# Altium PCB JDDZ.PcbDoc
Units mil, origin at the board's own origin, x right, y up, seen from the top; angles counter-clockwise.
Board outline 2165.35 x 2165.35 mil, 2 copper layers (Top Layer, Bottom Layer); 69 components, 50 nets, 275 pads, 93 vias.
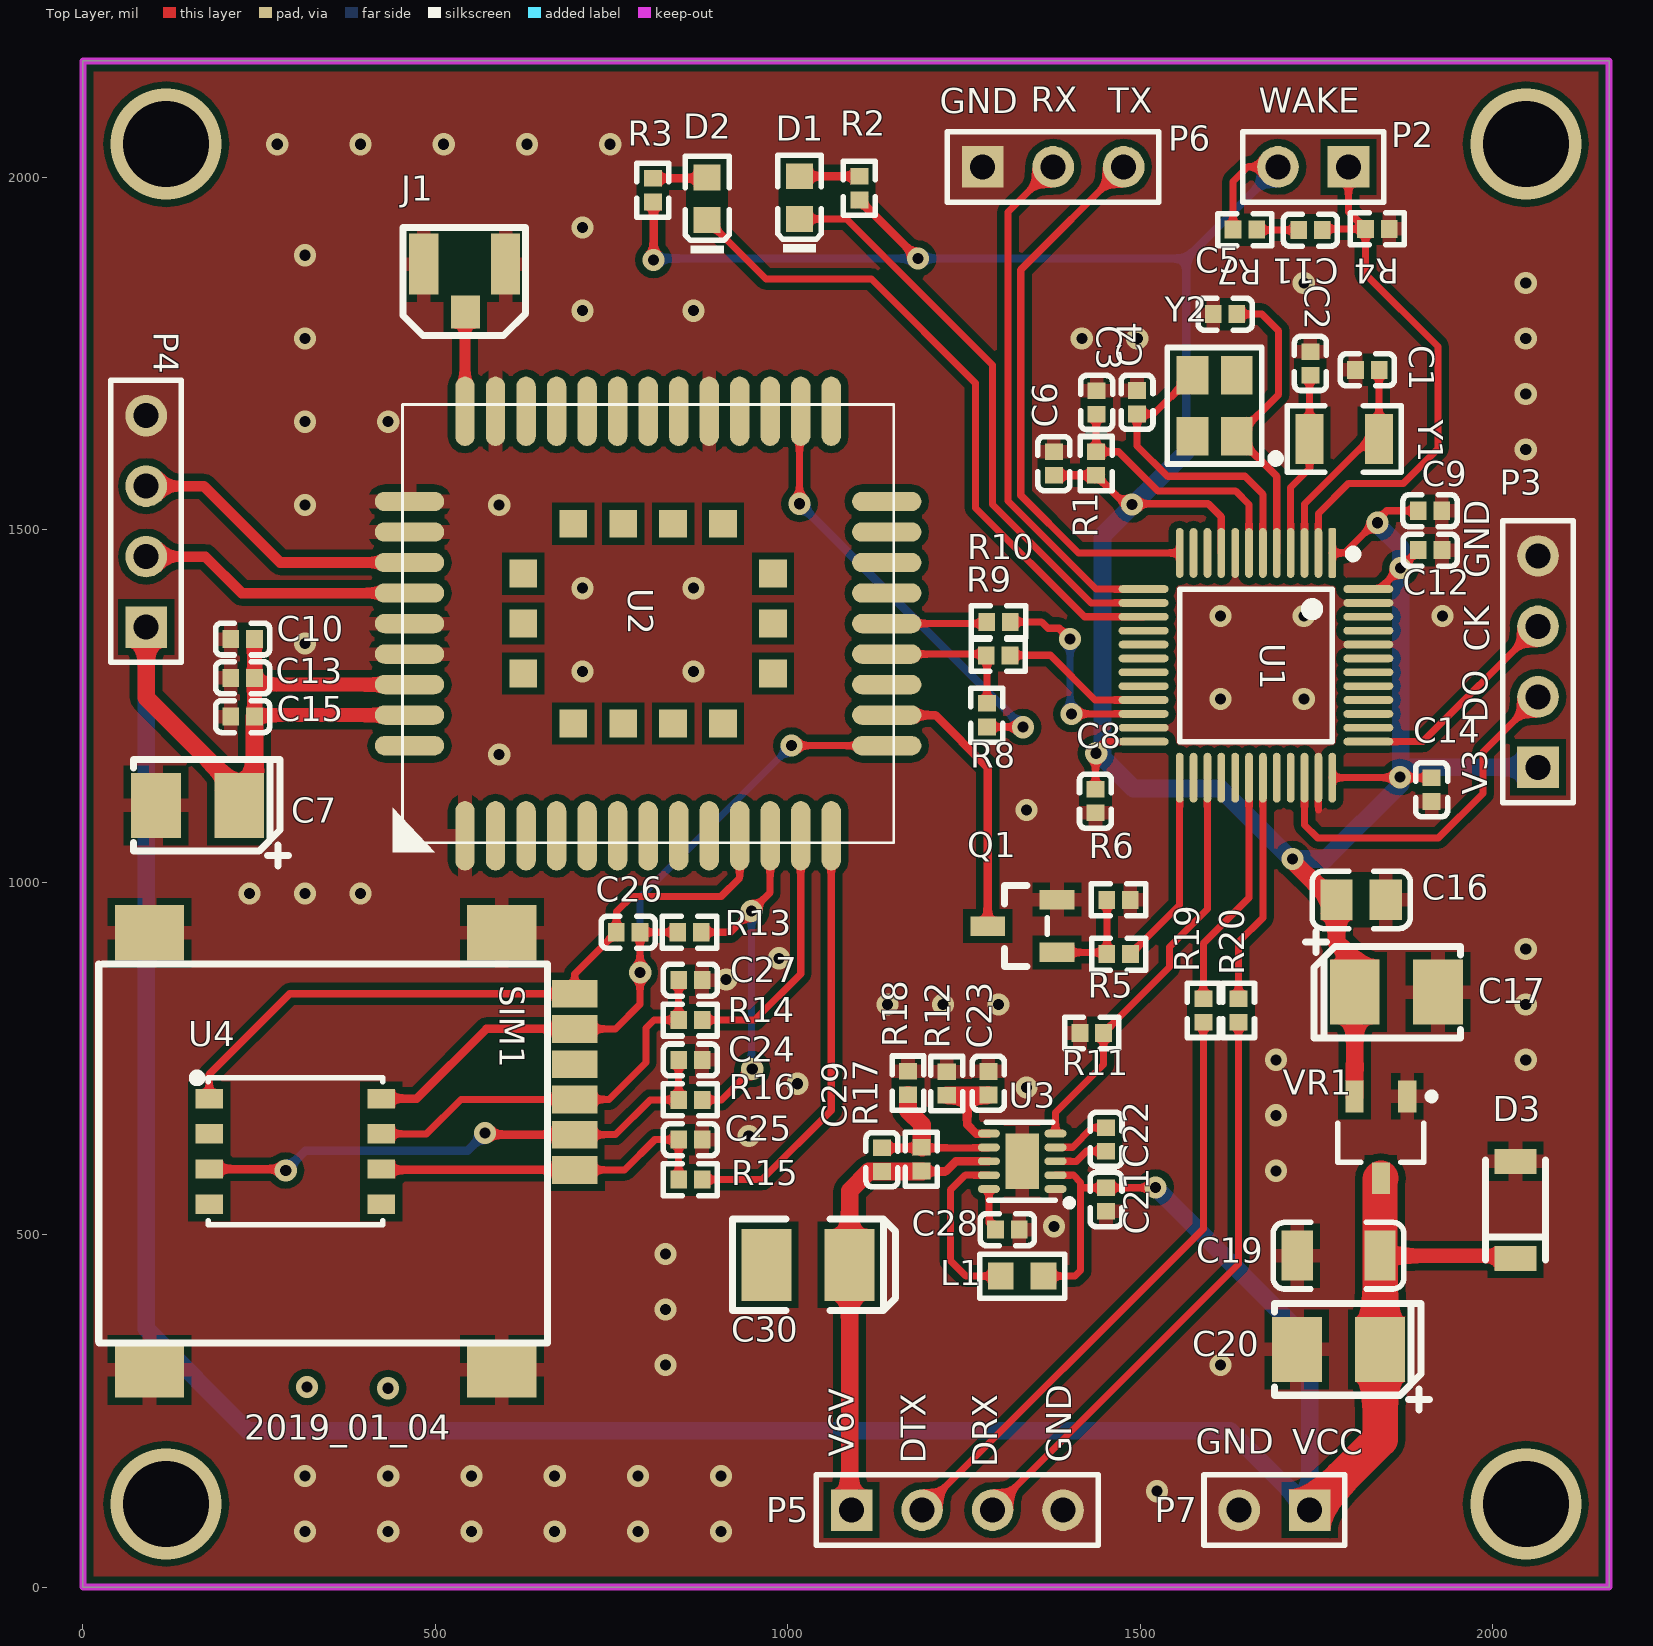
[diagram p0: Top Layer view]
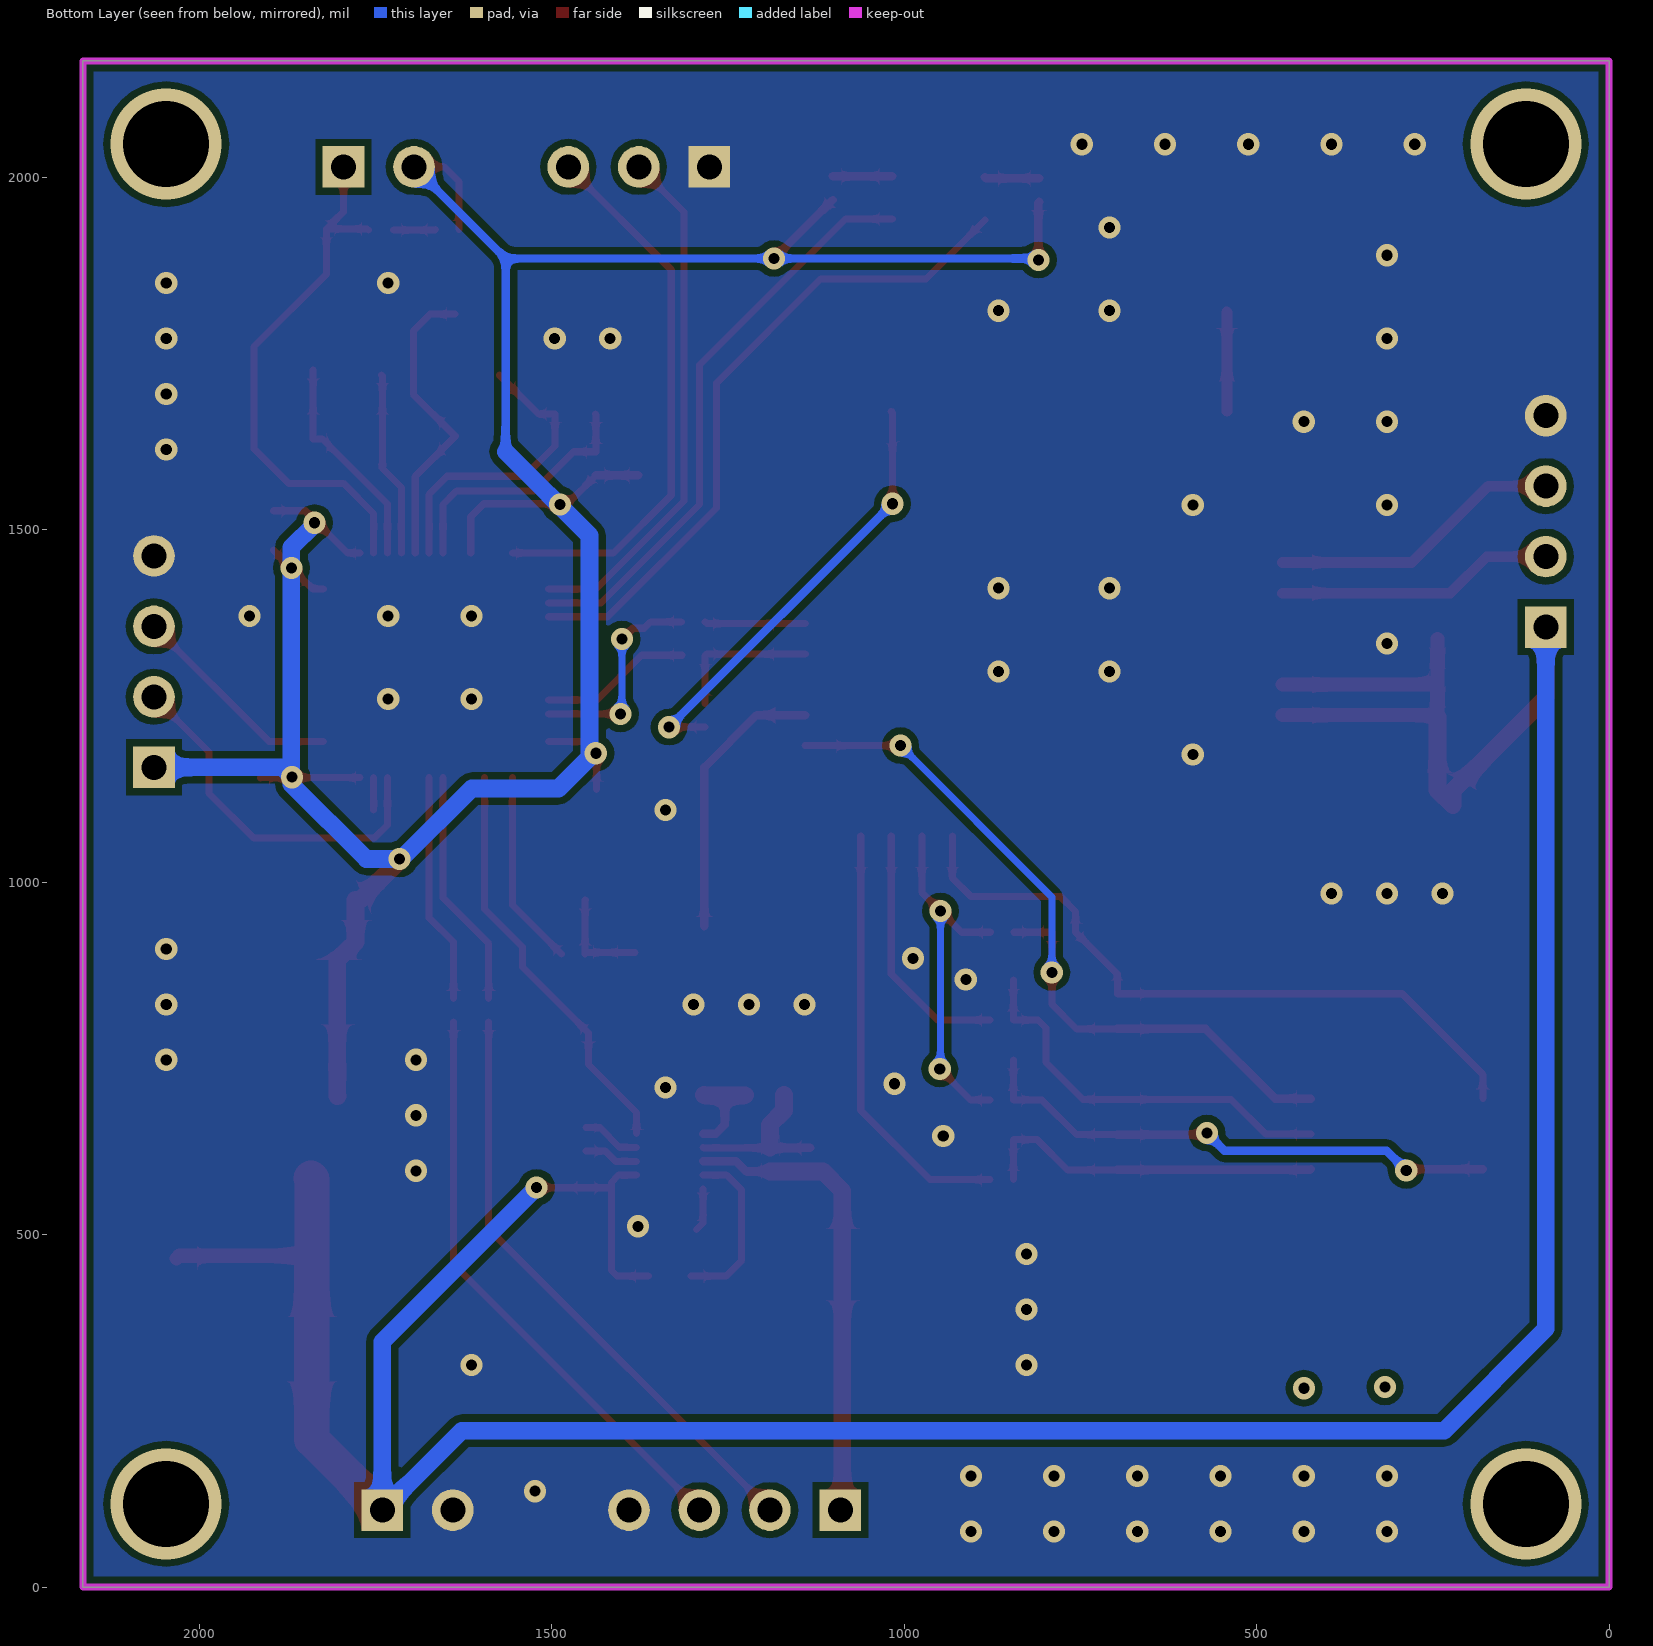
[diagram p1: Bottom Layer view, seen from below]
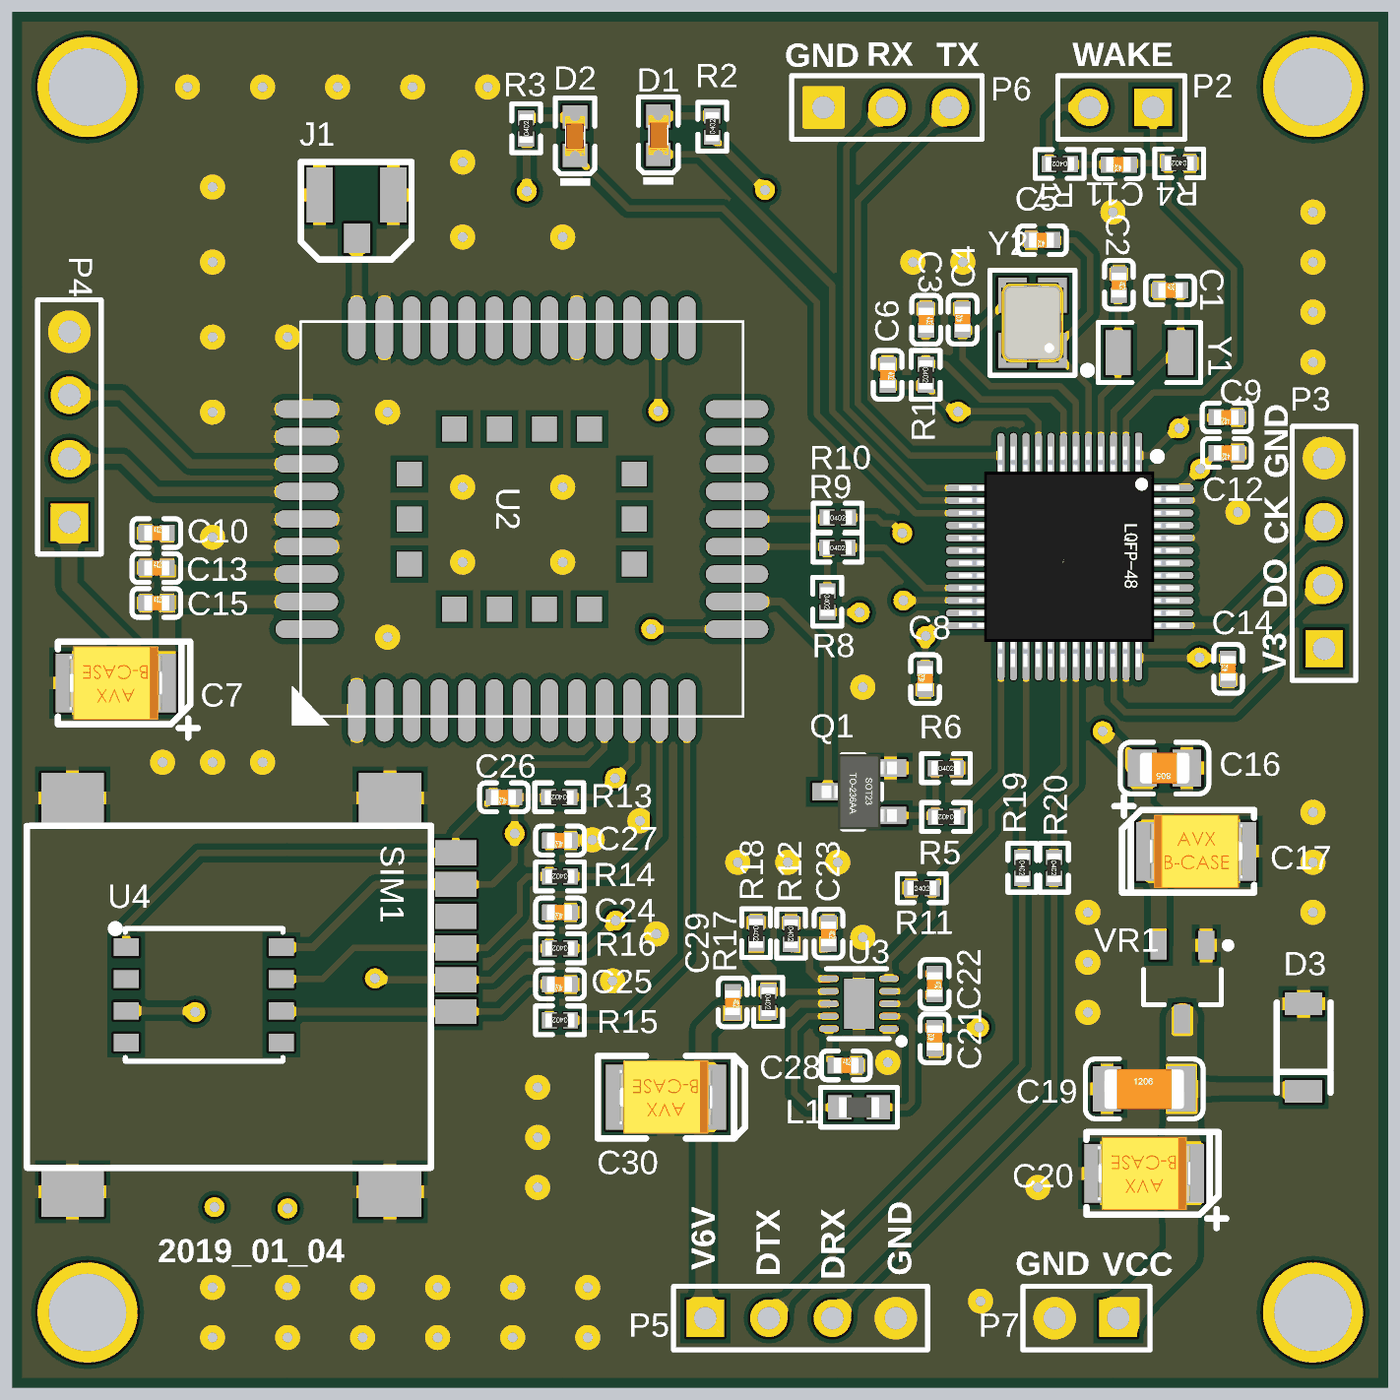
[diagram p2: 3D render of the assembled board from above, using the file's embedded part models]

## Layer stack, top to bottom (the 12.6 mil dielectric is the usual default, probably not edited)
Top Solder: solder mask 0.4, Solder Resist, Dk 3.5
Top Layer: signal copper 1.4
Dielectric 1: dielectric 12.6, FR-4, Dk 4.8
Bottom Layer: signal copper 1.4
Bottom Solder: solder mask 0.4, Solder Resist, Dk 3.5

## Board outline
0,0 0,2165.35 2165.35,2165.35 2165.35,0

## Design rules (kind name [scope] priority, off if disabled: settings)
Clearance Clearance_7 [InNamedPolygon('Top Layer-No Net 1')] p1: gap=10 ignorepadtopadclearanceinfootprint=FALSE except(0: Arc-Hole Track-Hole SMDPad-Hole THPad-Hole Via-Hole Fill-Hole Poly-Hole Region-Hole Text-Hole)
Clearance Clearance_6 [InNamedPolygon('Top Layer-No Net 1')] p2: gap=10 ignorepadtopadclearanceinfootprint=FALSE except(0: Arc-Hole Track-Hole SMDPad-Hole THPad-Hole Via-Hole Fill-Hole Poly-Hole Region-Hole Text-Hole)
Clearance Clearance_5 [InNamedPolygon('Top Layer-No Net 1')] p3: gap=10 ignorepadtopadclearanceinfootprint=TRUE except(0: Arc-Hole Track-Hole SMDPad-Hole THPad-Hole Via-Hole Fill-Hole Poly-Hole Region-Hole Text-Hole)
Clearance Clearance_4 [InNamedPolygon('Top Layer-No Net 1')] p4: gap=12 ignorepadtopadclearanceinfootprint=FALSE
Clearance Clearance_3 [InNamedPolygon('Top Layer-No Net 1')] p5: gap=12 ignorepadtopadclearanceinfootprint=FALSE
Clearance Clearance_2 [InPolygon] p6: gap=12 ignorepadtopadclearanceinfootprint=FALSE
Clearance Clearance_1 [InComponent('U3')] p7: gap=7 ignorepadtopadclearanceinfootprint=FALSE
Clearance [All] p8: gap=8 ignorepadtopadclearanceinfootprint=FALSE
ComponentClearance [All] p1 off: gap=10 collisioncheckmode=3 verticalgap=10 showdistances=FALSE
PolygonConnect PolygonConnect_1 [IsVia] p1: connectstyle=Direct reliefconductorwidth=10 reliefentries=4 polygonreliefangle="90 Angle" airgapwidth=10
PolygonConnect [All] p2: thpad.connectstyle=Direct thpad.reliefconductorwidth=10 thpad.reliefentries=4 thpad.polygonreliefangle="90 Angle" thpad.airgapwidth=10 smdpad.connectstyle=Relief smdpad.reliefconductorwidth=20 smdpad.reliefentries=4 smdpad.polygonreliefangle="90 Angle" smdpad.airgapwidth=10 via.connectstyle=Relief via.reliefconductorwidth=10 via.reliefentries=4 via.polygonreliefangle="90 Angle" via.airgapwidth=10
RoutingVias [All] p1: holewidth=28 width=50 viastyle="Through Hole" minholewidth=11.81 minwidth=23.62 maxholewidth=28 maxwidth=50
SolderMaskExpansion [All] p1: expansion=4
Width [All] p1: maxlimit=50 minlimit=10 preferedwidth=10
29 further rules are at their usual default settings.

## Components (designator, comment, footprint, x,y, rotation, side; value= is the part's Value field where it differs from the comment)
C1 "20pF (200) 5% 50V" 0402_C 1822.38,1727.15 r0 top
C2 "20pF (200) 5% 50V" 0402_C 1741.65,1736.15 r270 top
C3 "100nF (104) 10% 16V" 0402_C 1438.28,1680.8 r270 top
C4 "12pF (120) 5% 50V" 0402_C 1495.65,1681.09 r90 top
C5 "12pF (120) 5% 50V" 0402_C 1620.65,1806.09 r180 top
C6 "100nF (104) 10% 16V" 0402_C 1377.65,1594.09 r270 top
C7 "100uF (107) ±10% 6.3V" CASE-B_3528#1 162.65,1109.09 r180 top
C8 "100nF (104) 10% 16V" 0402_C 1436.65,1115.15 r90 top
C9 "100nF (104) 10% 16V" 0402_C 1911.38,1527.15 r180 top
C10 "100nF (104) 10% 16V" 0402_C 226.65,1345.09 r0 top
C11 "100nF (104) 10% 16V" 0402_C 1741.65,1925.36 r180 top
C12 "100nF (104) 10% 16V" 0402_C 1911.65,1471.15 r180 top
C13 "100nF (104) 10% 16V" 0402_C 226.65,1290.09 r0 top
C14 "100nF (104) 10% 16V" 0402_C 1913.65,1131.36 r90 top
C15 "22pF (220) 5% 50V" 0402_C 226.65,1235.09 r0 top
C16 "10uF (106) 10% 25V" 0805_C 1813.65,975.09 r180 top
C17 "100uF (107) ±10% 6.3V" CASE-B_3528#1 1863.65,844.09 r0 top
C19 "10uF (106) 10% 50V" 1206_C 1781.65,470.09 r0 top
C20 "100uF (107) ±10% 6.3V" CASE-B_3528#1 1781.65,337.09 r180 top
C21 "4.7uF (475) 20% 10V" 0402_C 1451.65,549.83 r90 top
C22 "100nF (104) 10% 16V" 0402_C 1451.65,635.09 r270 top
C23 "1.0uF (105) 10% 25V" 0402_C 1284.65,714.83 r270 top
C24 "33pF (330) 5% 50V" 0402_C 861.91,747.89 r180 top
C25 "33pF (330) 5% 50V" 0402_C 861.91,634.69 r180 top
C26 "100nF (104) 10% 16V" 0402_C 773.65,929.09 r180 top
C27 "33pF (330) 5% 50V" 0402_C 861.91,861.09 r180 top
C28 "100nF (104) 10% 16V" 0402_C 1311.65,507.09 r0 top
C29 "10nF (103) 10% 50V" 0402_C 1133.65,606.36 r270 top
C30 "100uF (107) ±10% 10V" CASE-B_3528#2 1028.7,457.09 r0 top
D1 "绿灯 0603" 0603_LED_S1 1016.75,1971.41 r90 top
D2 "红灯 0603" 0603_LED_S1 885.65,1969.83 r90 top
D3 "ZMM5V6" LL-34 2032.65,535.09 r90 top
J1 "SMB" IPX_SMT 483.5,1877.09 r0 top
L1 "10uH ±10%" 0603_L 1332.65,441.09 r180 top
P2 "Header 2" HDR1X2 1795.65,2015.09 r180 top
P3 "Header 4" HDR1X4 2064.65,1163.09 r90 top
P4 "Header 4" HDR1X4 89.65,1362.09 r90 top
P5 "Header 4" HDR1X4 1090.65,109.09 r0 top
P6 "Header 3" HDR1X3 1276.65,2015.09 r0 top
P7 "Header 2" HDR1X2 1740.65,109.09 r180 top
Q1 "SS8050 Y1" SOT-23(SOT-23-3) 1332.86,937.83 r0 top
R1 "47KΩ (4702) ±1%" 0402_R 1437.65,1594.15 r270 top
R2 "1KΩ (1001) ±1%" 0402_R 1101.65,1984.83 r90 top
R3 "1KΩ (1001) ±1%" 0402_R 808.65,1982.09 r90 top
R4 "4.7KΩ (4701) ±1%" 0402_R 1836.65,1927.09 r180 top
R5 "4.7KΩ (4701) ±1%" 0402_R 1469.65,898.09 r180 top
R6 "47KΩ (4702) ±1%" 0402_R 1469.38,975.09 r0 top
R7 "100Ω (1000) ±1%" 0402_R 1648.65,1926.09 r180 top
R8 "1MΩ (1004) ±1%" 0402_R 1282.65,1237.09 r270 top
R9 "1KΩ (1001) ±1%" 0402_R 1298.65,1322.09 r0 top
R10 "1KΩ (1001) ±1%" 0402_R 1299.1,1369.46 r0 top
R11 "10KΩ (1002) ±1%" 0402_R 1431.38,786.09 r0 top
R12 "200KΩ (2003) ±1%" 0402_R 1225.65,714.36 r270 top
R13 "10KΩ (1002) ±1%" 0402_R 860.65,929.09 r180 top
R14 "22Ω (22R0) ±1%" 0402_R 861.91,804.49 r180 top
R15 "22Ω (22R0) ±1%" 0402_R 861.91,578.09 r180 top
R16 "22Ω (22R0) ±1%" 0402_R 861.91,691.29 r180 top
R17 "150KΩ (1503) ±1%" 0402_R 1189.65,607.09 r270 top
R18 "10KΩ (1002) ±1%" 0402_R 1170.65,715.09 r270 top
R19 "22Ω (22R0) ±1%" 0402_R 1589.65,818.09 r270 top
R20 "22Ω (22R0) ±1%" 0402_R 1639.65,818.09 r270 top
SIM1 "SIM_CARD" microSIMauto 434.38,648.09 r270 top
U1 "STM32L151C8T6" LQFP-48_7x7x05P 1664.38,1307.83 r270 top
U2 "BC26/28" bc26 801.91,1367.09 r90 top
U3 "TPS61093DSKR" LC-WSON-10_2.5x2.5mm 1332.65,604.09 r90 top
U4 "SIM-SMT" SIM-SOP 301.65,618.09 r0 top
VR1 "XC6206P332MR" SOT-23-3L 1841.65,638.09 r90 top
Y1 "32.768KHz ±20ppm 12.5pF" "SMD-3215_2P FC - 135" 1789.65,1629.15 r0 top
Y2 "16MHZ 9PF 10PPM" SMD-3225_4P 1605.65,1676.15 r90 top

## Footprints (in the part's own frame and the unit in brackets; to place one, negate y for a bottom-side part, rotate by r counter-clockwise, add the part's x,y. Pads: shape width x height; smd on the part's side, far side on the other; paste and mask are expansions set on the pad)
0402_C [mm]
  rect 0.6x0.65 smd mask+0.051: 1(-0.425,0) 2(0.425,0)
  silkscreen extent -0.97,-0.58 0.97,0.58, body extent -0.48,-0.3 0.52,0.3, height 0.2
0402_R [mm]
  rect 0.6x0.65 smd mask+0.051: 1(-0.425,0) 2(0.425,0)
  silkscreen extent -0.97,-0.58 0.97,0.58, body extent -0.57,-0.27 0.58,0.28, height 0.41
0603_L [mm]
  rect 0.93x0.98 smd: 1(-0.77,0) 2(0.77,0)
  silkscreen extent -1.53,-0.79 1.54,0.79, body extent -0.82,-0.41 0.83,0.41, height 0.46
0603_LED_S1 [mm]
  rect 0.93x0.98 smd: A(0.77,0) K(-0.77,0)
  silkscreen extent -1.98,-0.79 1.54,0.79, body extent -0.8,-0.4 0.8,0.4, height 0.6
0805_C [mm]
  rect 1.16x1.47 smd: 1(-0.89,0) 2(0.89,0)
  silkscreen extent -1.77,-1.04 1.77,1.04, body extent -1,-0.62 1,0.63, height 0.77
1206_C [mm]
  rect 1.13x1.8 smd: 1(-1.49,0) 2(1.49,0)
  silkscreen extent -2.36,-1.2 2.35,1.2, body extent -1.6,-0.81 1.6,0.79, height 1
bc26 [mm]
  oval 2.5x0.7 smd mask+0.05: 1(-7.65,6.6) 2(-7.65,5.5) 3(-7.65,4.4) 4(-7.65,3.3) 5(-7.65,2.2) 6(-7.65,1.1) 7(-7.65,0) 8(-7.65,-1.1) 9(-7.65,-2.2) 10(-7.65,-3.3) 11(-7.65,-4.4) 12(-7.65,-5.5) 13(-7.65,-6.6) 23(7.65,-6.6) 24(7.65,-5.5) 25(7.65,-4.4) 26(7.65,-3.3) 27(7.65,-2.2) 28(7.65,-1.1) 29(7.65,0) 30(7.65,1.1) 31(7.65,2.2) 32(7.65,3.3) 33(7.65,4.4) 34(7.65,5.5) 35(7.65,6.6)
  oval 0.7x2.5 smd mask+0.05: 14(-4.4,-8.6) 15(-3.3,-8.6) 16(-2.2,-8.6) 17(-1.1,-8.6) 18(0,-8.6) 19(1.1,-8.6) 20(2.2,-8.6) 21(3.3,-8.6) 22(4.4,-8.6) 36(4.4,8.6) 37(3.3,8.6) 38(2.2,8.6) 39(1.1,8.6) 40(0,8.6) 41(-1.1,8.6) 42(-2.2,8.6) 43(-3.3,8.6) 44(-4.4,8.6)
  rect 1x1 smd mask+0.05: 45(-3.6,2.7) 46(-3.6,0.9) 47(-3.6,-0.9) 48(-3.6,-2.7) 49(-1.8,-4.5) 50(0,-4.5) 51(1.8,-4.5) 52(3.6,-2.7) 53(3.6,-0.9) 54(3.6,0.9) 55(3.6,2.7) 56(1.8,4.5) 57(0,4.5) 58(-1.8,4.5)
  silkscreen extent -8.25,-8.85 7.9,9.2
CASE-B_3528#1 [mm] "钽电容B型"
  rect 1.8x2.35 smd: 1(-1.5,0) 2(1.5,0)
  silkscreen extent -3.28,-1.65 2.31,2.18, body extent -1.85,-1.46 1.85,1.47, height 2.03
CASE-B_3528#2 [mm]
  rect 1.8x2.6 smd: 1(1.5,0) 2(-1.5,0)
  silkscreen extent -2.73,-1.65 3.16,1.65, body extent -1.85,-1.47 1.85,1.46, height 2.03
HDR1X2 [mm] "Connector; Header; 2 Position"
  rect 1.5x1.5 hole 0.9: 1(0,0)
  round 1.5 hole 0.9: 2(2.54,0)
  silkscreen extent -1.27,-1.27 3.81,1.27
HDR1X3 [mm] "Connector; Header; 3 Position"
  rect 1.5x1.5 hole 0.9: 1(0,0)
  round 1.5 hole 0.9: 2(2.54,0) 3(5.08,0)
  silkscreen extent -1.27,-1.27 6.35,1.27
HDR1X4 [mm] "Connector; Header; 4 Position"
  rect 1.5x1.5 hole 0.9: 1(0,0)
  round 1.5 hole 0.9: 2(2.54,0) 3(5.08,0) 4(7.62,0)
  silkscreen extent -1.27,-1.27 8.89,1.27
IPX_SMT [mm] "IPX"
  rect 1.05x1.2 smd: 1(1.5,-1.725)
  rect 1.05x2.2 smd: 2(0,0) 2(2.95,0)
  silkscreen extent -0.75,-2.58 3.67,1.33
LC-WSON-10_2.5x2.5mm [mm]
  rect 2x1.2 smd mask+0.051: 0(0,0)
  oval 0.28x0.8 smd paste-0.025 mask+0.051: 1(-1,-1.2) 2(-0.5,-1.2) 3(0,-1.2) 4(0.5,-1.2) 5(1,-1.2) 6(1,1.2) 7(0.5,1.2) 8(0,1.2) 9(-0.5,1.2) 10(-1,1.2)
  silkscreen extent -1.62,-1.82 1.4,1.3
LL-34 [mm]
  rect 0.9x1.5 smd: 1(1.75,0) 2(-1.75,0)
  silkscreen extent -1.8,-1.08 1.8,1.08
LQFP-48_7x7x05P [mm]
  rrect50% 1.8x0.28 smd mask+0.051: 1(-4.05,2.75)
  oval 1.8x0.28 smd mask+0.051: 2(-4.05,2.25) 3(-4.05,1.75) 4(-4.05,1.25) 5(-4.05,0.75) 6(-4.05,0.25) 7(-4.05,-0.25) 8(-4.05,-0.75) 9(-4.05,-1.25) 10(-4.05,-1.75) 11(-4.05,-2.25) 12(-4.05,-2.75) 25(4.05,-2.75) 26(4.05,-2.25) 27(4.05,-1.75) 28(4.05,-1.25) 29(4.05,-0.75) 30(4.05,-0.25) 31(4.05,0.25) 32(4.05,0.75) 33(4.05,1.25) 34(4.05,1.75) 35(4.05,2.25) 36(4.05,2.75)
  oval 0.28x1.8 smd mask+0.051: 13(-2.75,-4.05) 14(-2.25,-4.05) 15(-1.75,-4.05) 16(-1.25,-4.05) 17(-0.75,-4.05) 18(-0.25,-4.05) 19(0.25,-4.05) 20(0.75,-4.05) 21(1.25,-4.05) 22(1.75,-4.05) 23(2.25,-4.05) 24(2.75,-4.05) 37(2.75,4.05) 38(2.25,4.05) 39(1.75,4.05) 40(1.25,4.05) 41(0.75,4.05) 42(0.25,4.05) 43(-0.25,4.05) 44(-0.75,4.05) 45(-1.25,4.05) 46(-1.75,4.05) 47(-2.25,4.05) 48(-2.75,4.05)
  silkscreen extent -4.16,-2.75 2.75,3.65, body extent -4.41,-4.44 4.41,4.39, height 1.4
microSIMauto [mm]
  rect 1x1.65 smd: 1(-3.651,6.689) 2(-1.111,6.689) 3(1.429,6.689) 4(-4.921,6.689) 5(-2.381,6.689) 6(0.159,6.689)
  rect 2x2.5 smd: GND(-7.112,4.064) GND(-7.112,-8.636) GND(8.636,4.064) GND(8.636,-8.636)
  silkscreen extent -6,-10.46 7.67,5.7
SIM-SOP [mm]
  rect 1x0.7 smd: 1(-3.113,1.905) 2(-3.113,0.635) 3(-3.113,-0.635) 4(-3.113,-1.905) 5(3.088,-1.905) 6(3.088,-0.635) 7(3.088,0.635) 8(3.088,1.905)
  silkscreen extent -3.6,-2.65 3.15,2.7, body extent -2.82,-2.5 3.18,2.5, height 2.65
"SMD-3215_2P FC - 135" [mm]
  rect 1x1.8 smd: 1(-1.25,0) 2(1.25,0)
  silkscreen extent -2.05,-1.2 2.05,1.2
SMD-3225_4P [mm]
  rect 1.4x1.15 smd: 1(-1.1,-0.8) 2(1.1,-0.8) 3(1.1,0.8) 4(-1.1,0.8)
  silkscreen extent -2.1,-2.35 2.1,1.7, body extent -1.6,-1.25 1.6,1.25, height 0.61
SOT-23(SOT-23-3) [mm]
  rect 1.25x0.7 smd: 1(1.25,-0.95) 2(1.25,0.95) 3(-1.25,0)
  silkscreen extent -0.65,-1.46 0.9,1.46, body extent -1.5,-1.5 1.5,1.5, height 1.3
SOT-23-3L [mm] "http://www.aosmd.com/res/packaging_information/SOT-23-3L.pdf"
  rect 1.15x0.65 smd: 1(1.475,-0.95) 2(1.475,0.95) 3(-1.475,0)
  silkscreen extent -0.9,-1.95 1.6,1.55, body extent -0.9,-1.55 0.9,1.55, height 1.25

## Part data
C1 C2: library part "0402 20pF (200) 5% 50V", "贴片电容", Package=0402, SuppliersPartNumber=C1554
C3 C6 C8 C9 C10 C11 C12 C13 C14 C22 C26 C28: library part "0402 100nF (104) 10% 16V", "贴片电容", Package=0402, SuppliersPartNumber=C1525
C4 C5: library part "0402 12pF (120) 5% 50V", "贴片电容", Package=0402, SuppliersPartNumber=C1547
C7 C17 C20 C30: library part "3528 100uF (107) 10% 6.3V", "钽电容", Package=3528, SuppliersPartNumber=C16133
C15: library part "0402 22pF (220) 5% 50V", "贴片电容", Package=0402, SuppliersPartNumber=C1555
C16: library part "0805 10uF (106) 10% 25V", "贴片电容", Package=0805, SuppliersPartNumber=C15850
C19: library part "1206 10uF (106) 10% 50V", "贴片电容", Package=1206, SuppliersPartNumber=C13585
C21: library part "0402 4.7uF (475) 20% 10V", "贴片电容", Package=0402, SuppliersPartNumber=C23733
C23: library part "0402 1.0uF (105) 10% 25V", "贴片电容", Package=0402, SuppliersPartNumber=C52923
C24 C25 C27: library part "0402 33pF (330) 5% 50V", "贴片电容", Package=0402, SuppliersPartNumber=C1562
C29: library part "0402 10nF (103) 10% 50V", "贴片电容", Package=0402, SuppliersPartNumber=C15195
D1: library part "0603 绿灯", "发光二极管", Package=0603, SuppliersPartNumber=C72043
D2: library part "0603 红灯", "发光二极管", Package=0603, SuppliersPartNumber=C2286
D3: library part "LL-34 ZMM5V6", "稳压二极管", Package=LL-34, SuppliersPartNumber=C8062
J1: "SMB Straight Connector"
L1: library part "0603 10uH 10%", "贴片电感", Package=0603, SuppliersPartNumber=C1035
P2 P7: "Header, 2-Pin"
P3 P4 P5: "Header, 4-Pin"
P6: "Header, 3-Pin"
Q1: library part "SOT-23 SS8050 Y1", "三极管", Package=SOT-23, SuppliersPartNumber=C2150
R1 R6: library part "0402 47KΩ (4702) 1%", "贴片电阻", Package=0402, SuppliersPartNumber=C25792
R2 R3 R9 R10: library part "0402 1KΩ (1001) 1%", "贴片电阻", Package=0402, SuppliersPartNumber=C11702
R4 R5: library part "0402 4.7KΩ (4701) 1%", "贴片电阻", Package=0402, SuppliersPartNumber=C25900
R7: library part "0402 100Ω (1000) 1%", "贴片电阻", Package=0402, SuppliersPartNumber=C25076
R8: library part "0402 1MΩ (1004) 1%", "贴片电阻", Package=0402, SuppliersPartNumber=C26083
R11 R13 R18: library part "0402 10KΩ (1002) 1%", "贴片电阻", Package=0402, SuppliersPartNumber=C25744
R12: library part "0402 200KΩ (2003) 1%", "贴片电阻", Package=0402, SuppliersPartNumber=C25764
R14 R15 R16 R19 R20: library part "0402 22Ω (22R0) 1%", "贴片电阻", Package=0402, SuppliersPartNumber=C25092
R17: library part "0402 150KΩ (1503) 1%", "贴片电阻", Package=0402, SuppliersPartNumber=C25755
U1: "ARM", Package=LQFP-48_7x7x05P, SuppliersPartNumber=C9861
U2: library part BC26
VR1: library part "SOT-23 XC6206P332MR", "低压差线性稳压(LDO)", Package=SOT-23, SuppliersPartNumber=C5446
Y1: library part "SMD-3215_2P 32.768KHz 20ppm 12.5pF", "贴片晶振", Package=SMD-3215_2P, SuppliersPartNumber=C32346
Y2: library part "SMD-3225_4P  16MHZ 9PF 10PPM", "贴片晶振", Package=SMD-3225_4P, SuppliersPartNumber=C13738

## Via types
v1: diameter 31.5, hole 15.75, Top Layer to Bottom Layer, 89 vias
v2: diameter 157.48, hole 122.05, Top Layer to Bottom Layer, 4 vias

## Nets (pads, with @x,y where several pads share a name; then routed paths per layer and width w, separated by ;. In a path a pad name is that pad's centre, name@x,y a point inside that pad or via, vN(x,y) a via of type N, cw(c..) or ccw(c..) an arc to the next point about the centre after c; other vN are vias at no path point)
BATVCC: C7.1 C10.2 C13.2 C15.2 C19.2 C20.1 C21.2 D3.2 L1.1 P4.1 P7.1 U2.42 U2.43 U3.2 VR1.3 | length 5334.3
  Top Layer w10: L1.1 1407.65,441.09 1415.65,449.09 1415.65,565.09 ; U3.2 1405.33,584.41 1415.65,574.09 1415.65,565.09 ; v1(1521.65,567.09) 1521.11,566.56 C21.2 1417.11,566.56 1415.65,565.09
  Top Layer w20: C10.2 C13.2 ; U2.43 245.46,1237.17 C15.2 C13.2 ; U2.42 252.99,1280.48 C13.2 ; C19.2 2028.75,470.09 D3.2
  Top Layer w25: P4.1 89.65,1262.09 221.7,1130.04 C7.1 243.38,1130.77 C15.2
  Top Layer w50: P7.1 1840.7,209.15 C20.1 1840.7,469.7 C19.2 1840.31,578.69 VR1.3
  Bottom Layer w25: P4.1 89.65,366.35 234,222 1627.74,222 P7.1 1740.65,348.09 v1(1521.65,567.09)
BC28_RESET: Q1.3 U2.15 | length 399.1
  Top Layer w12: U2.15 1209.57,1237.17 1283.65,1163.09 Q1.3
BC28_RX: R8.1 R9.1 U2.17 | length 210.7
  Top Layer w10: U2.17 1280.22,1323.79 R9.1 1282.65,1321.36 R8.1
BC28_TX: R10.1 U2.18 | length 142.9
  Top Layer w10: U2.18 1280.01,1367.09 R10.1
BLUE_LED: D1.K U1.14 | length 829.8
  Top Layer w10: D1.K 1083.65,1941.09 1290.65,1734.09 1290.65,1536.09 1430.33,1396.41 U1.14
DEBUG_RX: P6.2 U1.13 | length 744.6
  Top Layer w10: P6.2 1312.65,1951.09 1312.65,1541.09 1437.65,1416.09 U1.13
DEBUG_TX: P6.3 U1.12 | length 785.8
  Top Layer w10: P6.3 1330.65,1869.09 1330.65,1549.09 1412.46,1467.28 U1.12
DY_EN: R11.2 U1.27 U3.5 | length 594.2
  Top Layer w10: U3.5 1379.89,673.34 1448.11,741.56 R11.2 1541.65,879.63 1541.65,908.09 1595.48,961.93 U1.27
GND: C1.1 C2.1 C3.1 C4.2 C5.2 C6.1 C7.2 C8.1 C9.1 C10.1 C12.1 C13.1 C14.1 C15.1 C16.1 C17.2 C19.1 C20.2 C21.1 C23.1 C24.1 C25.1 C27.1 C28.2 D3.1 J1.2 P3.4 P4.4 P5.4 P6.1 P7.2 Q1.2 R4.1 R6.2 R11.1 R12.1 R18.1 SIM1.GND U1.8 U1.23 U1.35 U1.44 U1.47 U2.1 U2.27 U2.34 U2.36 U2.37 U2.40 U2.41 U3.0 U3.1 VR1.1 | length 45.6
  Top Layer w10: 1752.96,1102.78 U1.35
  other v1: 314.96,78.74 433.07,78.74 551.18,78.74 669.29,78.74 787.4,78.74 905.51,78.74 1524,136 314.96,157.48 433.07,157.48 551.18,157.48 669.29,157.48 787.4,157.48 905.51,157.48 826.77,314.96 1614.17,314.96 826.77,393.7 826.77,472.44 1377.95,511.81 1692.91,590.55 944.65,640.09 1692.91,669.29 1338.58,708.66 1013.65,714.09 1692.91,748.03 2047.24,748.03 1141.73,826.77 1220.47,826.77 1299.21,826.77 2047.24,826.77 912.65,862.09 987.65,892.09 2047.24,905.51 236.22,984.25 314.96,984.25 393.7,984.25 1338.58,1102.36 590.55,1181.1 1614.17,1259.84 1732.28,1259.84 708.66,1299.21 866.14,1299.21 314.96,1338.58 1614.17,1377.95 1732.28,1377.95 1929.13,1377.95 708.66,1417.32 866.14,1417.32 314.96,1535.43 590.55,1535.43 2047.24,1614.17 314.96,1653.54 433.07,1653.54 2047.24,1692.91 314.96,1771.65 1417.32,1771.65 1496.06,1771.65 2047.24,1771.65 708.66,1811.02 866.14,1811.02 1732.28,1850.39 2047.24,1850.39 314.96,1889.76 708.66,1929.13 275.59,2047.24 393.7,2047.24 511.81,2047.24 629.92,2047.24 748.03,2047.24
NetC1_2: C1.2 U1.3 Y1.2 | length 311.4
  Top Layer w10: U1.3 1733.28,1536.72 1825.7,1629.15 Y1.2 1838.86,1726.9 C1.2
NetC2_2: C2.2 U1.4 Y1.1 | length 263.8
  Top Layer w10: U1.4 1713.59,1560.04 1740.43,1586.88 Y1.1 1740.43,1718.2 C2.2
NetC4_1: C4.1 U1.6 Y2.3 | length 436.8
  Top Layer w10: Y2.3 1519.06,1664.36 C4.1 1495.65,1619.09 1538.65,1576.09 1648.65,1576.09 1674.22,1550.52 U1.6
NetC5_1: C5.1 U1.5 Y2.1 | length 432.2
  Top Layer w10: C5.1 1672.65,1806.09 1696.65,1782.09 1696.65,1692.35 Y2.1 1693.91,1576.08 U1.5
NetC11_2: C11.2 R7.1 | length 59.8
  Top Layer w10: R7.1 1666.11,1925.36 C11.2
NetC22_1: C22.1 U3.4 | length 83.4
  Top Layer w10: U3.4 1403.87,623.78 1431.92,651.83 C22.1
NetC22_2: C22.2 U3.3 | length 77.7
  Top Layer w10: U3.3 1409.65,604.09 1423.91,618.36 C22.2
NetC23_2: C23.2 R12.2 U3.6 | length 137.8
  Top Layer w12: 1254.65,697.63 1254.65,656.09 1267.28,643.46 U3.6
  Top Layer w20: C23.2 C23.2@1285.4,697.34
  Top Layer w25: R12.2 1254.65,697.63 1284.18,697.63 C23.2
NetC24_2: C24.2 R16.2 SIM1.6 U4.3 | length 766.9
  Top Layer w10: v1@285.65,593.09 v1(287.65,591.09) ; v1(570.65,644.09) v1@572.9,641.84 ; SIM1.6 755.39,641.84 804.85,691.29 R16.2 C24.2
  Top Layer w12: U4.3 v1@285.65,593.09 ; v1@572.9,641.84 SIM1.6
  Bottom Layer w12: v1(287.65,591.09) 315.65,619.09 545.65,619.09 v1(570.65,644.09)
NetC25_2: C25.2 R15.2 SIM1.3 U4.6 | length 496.8
  Top Layer w10: SIM1.3 768.39,591.84 811.25,634.69 C25.2 R15.2
  Top Layer w12: U4.6 424.47,591.84 SIM1.3
NetC27_2: C27.2 R14.2 SIM1.2 U4.7 | length 574.1
  Top Layer w10: U4.7 487.65,643.09 536.39,691.84 SIM1.2 746.39,691.84 798.65,744.09 798.65,793.09 810.05,804.49 R14.2 C27.2
NetC28_1: C28.1 U3.10 | length 61.6
  Top Layer w10: U3.10 1285.4,516.61 C28.1
NetC29_1: C29.1 R17.1 R18.2 U3.7 | length 235.6
  Top Layer w10: R17.1@1190.65,623.09 1284.72,623.09 U3.7
  Top Layer w12: C29.1 R17.1@1190.65,623.09
  Top Layer w25: R18.2 1170.65,676.09 1190.65,656.09 R17.1@1190.65,623.09
NetD1_A: D1.A R2.2 | length 85
  Top Layer w12: D1.A 1101.48,2001.72 R2.2
NetD2_A: D2.A R3.2 | length 77.5
  Top Layer w12: R3.2 884.33,1998.83 D2.A
NetJ1_1: J1.1 U2.35 | length 141.1
  Top Layer w15: U2.35 542.07,1808.69 J1.1
NetL1_2: L1.2 U3.9 | length 244.4
  Top Layer w10: U3.9 1251.96,584.41 1230.65,563.09 1230.65,463.09 1252.65,441.09 L1.2
NetP5_2: P5.2 R19.2 | length 857.5
  Top Layer w10: P5.2 1589.65,508.09 R19.2
NetP5_3: P5.3 R20.2 | length 836.8
  Top Layer w10: P5.3 1639.65,458.09 R20.2
NetQ1_1: Q1.1 R5.2 R6.1 | length 148.9
  Top Layer w10: Q1.1 1450.58,900.43 R5.2 1452.91,974.83 R6.1
PWRKEY: U2.7
RED_LED: D2.K U1.15 | length 956.1
  Top Layer w10: D2.K 969.06,1856.09 1118.65,1856.09 1266.65,1708.09 1266.65,1531.09 1421.02,1376.72 U1.15
RESET: C3.2 R1.1 U1.7 | length 370.2
  Top Layer w10: C3.2 1437.65,1663.43 R1.1 1469.32,1610.88 1525.11,1555.09 1635.65,1555.09 1654.54,1536.2 U1.7
RXD_DBG: P4.3 U2.38 | length 418.6
  Top Layer w15: P4.3 171.65,1562.09 280.03,1453.71 U2.38
SIM_CLK: R15.1 U2.13 | length 613.5
  Top Layer w10: R15.1 963.65,578.09 1061.76,676.2 U2.13
SIM_DATA: R13.1 R16.1 U2.11 | length 515
  Top Layer w10: R13.1 918.65,929.09 v1(948.65,959.09) 975.14,985.59 U2.11 ; R16.1 905.85,691.29 v1(949.65,735.09)
  Bottom Layer w10: v1(948.65,959.09) 948.65,736.09 v1(949.65,735.09)
SIM_GND: C26.2 SIM1.4 U2.10 U4.1 | length 995.9
  Top Layer w10: U4.1 179.08,727.53 293.39,841.84 SIM1.4 697.71,869.89 C26.2 756.91,958.36 778.65,980.09 905.65,980.09 931.83,1006.28 U2.10
SIM_RST: R14.1 U2.12 | length 362.9
  Top Layer w10: R14.1 953.05,804.49 1018.45,869.9 U2.12
SIM_VCC: C26.1 R13.2 SIM1.1 U2.14 U4.8 | length 1131.2
  Top Layer w10: SIM1.1 755.39,791.84 790.38,826.83 v1@790.38,871.83 ; v1@785.65,867.09 v1@790.38,871.83 ; v1(790.65,872.09) v1@790.38,871.83 ; R13.2 C26.1 v1@790.38,871.83 ; v1(1005.42,1193.87) U2.14
  Top Layer w12: U4.8 473.65,693.09 572.39,791.84 SIM1.1
  Bottom Layer w10: v1(790.65,872.09) 790.65,979.09 v1(1005.42,1193.87)
STM32_DRX: R20.1 U1.31 | length 328
  Top Layer w10: R20.1 1639.65,915.09 1674.22,949.67 U1.31 U1.31@1674.16,1148.32
STM32_DTX: R19.1 U1.30 | length 340.4
  Top Layer w10: R19.1 1589.65,913.09 1654.54,977.98 U1.30
STM32_RESET: R5.1 U1.25 | length 279.2
  Top Layer w10: R5.1 1556.11,967.83 U1.25
STM32_RX: R10.2 U1.22 | length 304.3
  Top Layer w10: R10.2 1360.37,1369.46 1369.42,1360.41 1385.33,1360.41 v1(1400.65,1345.09) ; v1(1402.48,1238.93) U1.22
  Bottom Layer w10: v1(1400.65,1345.09) 1400.65,1240.76 v1(1402.48,1238.93)
STM32_TX: R9.2 U1.21 | length 215.8
  Top Layer w10: R9.2 1372.65,1322.09 1436.13,1258.61 U1.21
SWCLK: P3.3 U1.37 | length 308.6
  Top Layer w10: U1.37 1901.11,1199.56 P3.3
SWDIO: P3.2 U1.34 | length 523.3
  Top Layer w10: U1.34 1733.28,1081.46 1751.65,1063.09 1923.65,1063.09 1986.65,1126.09 1986.65,1185.09 P3.2
TEVS_VCC: C29.2 C30.1 P5.1 R17.2 U3.8 | length 669.3
  Top Layer w12: R17.2@1190.65,589.63 1224.18,589.63 1238.65,604.09 U3.8
  Top Layer w25: P5.1 1087.76,111.98 C30.1 1087.76,562.2 1115.18,589.63 C29.2 R17.2@1190.65,589.63
TXD_DBG: P4.2 U2.39 | length 395.1
  Top Layer w15: P4.2 173.65,1462.09 225.34,1410.4 U2.39
VCC_STM32: C6.2 C8.2 C9.2 C12.2 C14.2 C16.2 C17.1 P2.2 P3.1 R1.2 R2.1 R3.1 R7.2 U1.1 U1.9 U1.24 U1.36 U1.48 VR1.2 | length 4352.5
  Top Layer w10: C8.2 1436.65,1186.09 1450.11,1199.56 U1.24 ; R1.2 1477.97,1537.09 1596.65,1537.09 1615.17,1518.57 U1.9 ; R7.2 1631.91,1994.36 1652.65,2015.09 P2.2 ; U1.36 1913.36,1148.38 C14.2 ; U1.1 1789.83,1467.28 1849.7,1527.15 C9.2 ; U1.48 1839.86,1416.09 C12.2
  Top Layer w12: R3.1 809.65,1964.36 v1(809.65,1883.09) ; R2.1 v1(1184.65,1885.09) ; C6.2 1437.59,1577.36 R1.2
  Top Layer w25: v1(1716.15,1033.09) 1716.15,1030.59 1771.65,975.09 C16.2 1778.61,915.13 1804.59,889.15 C17.1 1804.59,696.51 VR1.2
  Bottom Layer w12: v1@811.65,1885.09 v1(1184.65,1885.09) 1565.65,1885.09 ; 1565.65,1611.09 1565.65,1885.09 ; P2.2 1565.65,1885.09
  Bottom Layer w25: v1(809.65,1883.09) v1@811.65,1885.09 ; 1565.65,1611.09 1446.65,1492.09 1446.65,1177.09 1490.65,1133.09 1613.65,1133.09 1713.65,1033.09 v1(1716.15,1033.09) 1763.65,1033.09 1869.65,1139.09 v1@1869.65,1150.09 ; v1(1836.65,1510.09) 1836.65,1508.09 1869.65,1475.09 v1(1869.65,1446.09) v1@1869.65,1150.09 ; v1(1868.65,1149.09) v1@1869.65,1150.09 ; P3.1 1882.65,1163.09 v1@1869.65,1150.09
  other v1: 1437.65,1183.09 1488.65,1536.09
VDD_EXT: R8.2 U2.24 | length 631.3
  Top Layer w10: v1(1016.65,1537.09) 1016.65,1666.47 U2.24 ; R8.2 1333.38,1220.36 v1(1333.65,1220.09)
  Bottom Layer w12: v1(1016.65,1537.09) v1(1333.65,1220.09)
WAKE: C11.1 P2.1 R4.2 U1.2 | length 776.7
  Top Layer w10: U1.2 1752.96,1523.41 1795.65,1566.09 1873.65,1566.09 1922.65,1615.09 1922.65,1760.09 1819.91,1862.83 R4.2 ; C11.1@1760.38,1925.36 1762.11,1927.09 R4.2 ; P2.1 1795.65,1951.36 R4.2
pads on no net: C30.2 SIM1.5 U1.10 U1.11 U1.16 U1.17 U1.18 U1.19 U1.20 U1.26 U1.28 U1.29 U1.32 U1.33 U1.38 U1.39 U1.40 U1.41 U1.42 U1.43 U1.45 U1.46 U2.2 U2.3 U2.4 U2.5 U2.6 U2.8 U2.9 U2.16 U2.19 U2.20 U2.21 U2.22 U2.23 U2.25 U2.26 U2.28 U2.29 U2.30 U2.31 U2.32 U2.33 U2.44 U2.45 U2.46 U2.47 U2.48 U2.49 U2.50 U2.51 U2.52 U2.53 U2.54 U2.55 U2.56 U2.57 U2.58 U4.2 U4.4 U4.5 Y2.2 Y2.4
copper on no net:
  other v1: 433,282 318,284
  other v2: 118.11,118.11 2047.24,118.11 118.11,2047.24 2047.24,2047.24

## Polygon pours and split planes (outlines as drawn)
GND on Bottom Layer "Top Layer-No Net 1" (solid, remove dead copper, pour order 7): 0,2165.35 0,0 2165.35,0 2165.35,2165.35
GND on Top Layer "Top Layer-No Net 1" (solid, remove dead copper, pour order 6): 0,2165.35 0,0 2165.35,0 2165.35,2165.35

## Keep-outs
Keep-Out Layer:
  the board outline again, w10

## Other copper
Top Layer:
  pour cut-out: 507.51,1930.4 507.51,1837.23 507.65,1837.09 574.65,1837.09 574.65,1929.54 573.78,1930.4

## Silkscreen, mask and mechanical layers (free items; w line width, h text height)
Top Overlay:
  text "RX" at 1344.65,2081.09 h60
  text "TX" at 1454.65,2080.09 h60
  text "WAKE" at 1668.65,2080.09 h60
  text "GND" at 1215.65,2079.09 h60
  text "GND" at 2007.65,1431.09 h60 r90
  text "CK" at 2007.65,1327.09 h60 r90
  text "DO" at 2005.65,1226.09 h60 r90
  text "V3" at 2004.65,1124.09 h60 r90
  text "2019_01_04" at 228.65,197.09 h60
  text "V6V" at 1105.65,185.09 h60 r90
  text "GND" at 1578.65,177.09 h60
  text "GND" at 1414.65,176.09 h60 r90
  text "VCC" at 1715.65,176.09 h60
  text "DTX" at 1207.65,175.09 h60 r90
  text "DRX" at 1309.65,170.09 h60 r90
Mechanical 1:
  the board outline again, w10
